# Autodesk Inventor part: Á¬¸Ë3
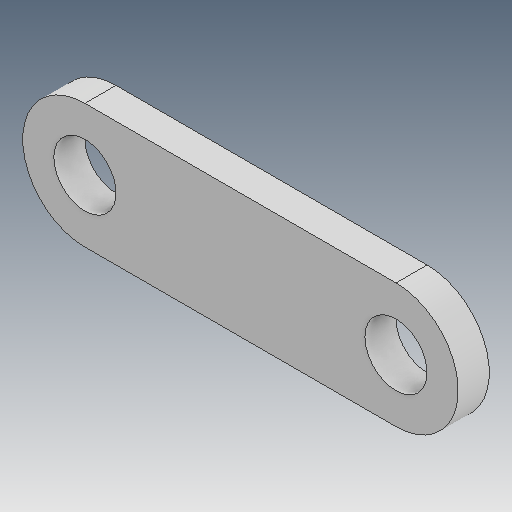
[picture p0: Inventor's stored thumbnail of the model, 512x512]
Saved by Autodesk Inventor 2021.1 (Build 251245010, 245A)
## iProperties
Created: 2014-12
Part Number: Á¬¸Ë3
Material: Ogólny
Document SubType Name: Modeling
Designer: user
Density: 1 g/cm^3
Appearance: Domyślna
Author: user
Revision Number: ÈÎºÎ
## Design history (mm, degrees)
feature "ÊäÈë1"
node "Bryła1"
